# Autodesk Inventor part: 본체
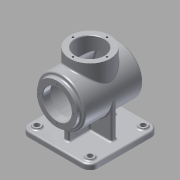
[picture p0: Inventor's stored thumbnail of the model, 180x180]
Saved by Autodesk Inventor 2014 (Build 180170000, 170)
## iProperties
Created: 2015-07
Part Number: 본체
Material: 알루미늄 6061
Document SubType Name: Modeling
Designer: L-10
Density: 2.71 g/cm^3
Appearance: 알루미늄 - 평지
Mass: 1277.59 g
Surface Area: 1269.15 cm^2
Volume: 471.436 cm^3
Author: L-10
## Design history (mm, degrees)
sketch "스케치2"
  geometry: C1 r 45 at (0, 0); 1 further point
  constraints: 1 centre point, 1 coincident
  dimensions: "d0" = 90 diameter of C1
extrude "돌출1" new body sketch "스케치2" stored distance "d1" = 110; taper "d2" = 0 deg
node "작업 평면1"
sketch "스케치3"
  geometry: L1 (-65, -65)-(65, -65); L2 (65, -65)-(65, 65); L3 (65, 65)-(-65, 65); L4 (-65, 65)-(-65, -65); 3 further points
  constraints: 8 end point, 2 midpoint, 2 parallel, 1 horizontal, 1 horizontal alignment, 1 perpendicular, 1 vertical alignment
  dimensions: "d4" = 130 distance of L2.end L3.end; "d5" = 130 distance of L3.end L1.start
extrude "돌출2" join sketch "스케치3" distance "d6" = 10; taper "d7" = 0 deg
sketch "스케치4"
  geometry: C1 r 45 at (0, 0) reference; C2 r 38 at (0, 0)
  constraints: 1 centre point, 1 coincident
  dimensions: "d8" = 76 diameter of C2
extrude "돌출3" join sketch "스케치4" distance "d9" = 7; taper "d10" = 0 deg
sketch "스케치5"
  geometry: L1 (-65, 65)-(-65, -65) reference; L2 (-5, 45)-(-5, 5); L3 (-5, 5)-(-45, 5); L4 (-45, 5)-(-45, -5); L5 (-45, -5)-(-5, -5); L6 (-5, -5)-(-5, -45); L7 (-5, -45)-(5, -45); L8 (5, -45)-(5, -5); L9 (5, -5)-(45, -5); L10 (45, -5)-(45, 5); L11 (45, 5)-(5, 5); L12 (5, 5)-(5, 45); L13 (5, 45)-(-5, 45); 3 further points
  constraints: 24 end point, 9 parallel, 6 collinear, 2 midpoint, 1 horizontal alignment, 1 perpendicular, 1 vertical alignment
  dimensions: "d11" = 10 distance of L9.end L10.end; "d12" = 10 distance of L12.end L2.start; "d13" = 90 distance between parallel lines of L7 L13; "d14" = 90 distance between parallel lines of L10 L4; "d15" = 45 distance from line of L4 point (0, 0) (= 0.5 x d14); "d16" = 45 distance from line of point (0, 0) L13 (= 0.5 x d13)
extrude "돌출4" join sketch "스케치5" stored distance "d17" = 7; taper "d18" = 0 deg
node "작업 평면2"
sketch "스케치6"
  geometry: C1 r 38 at (0, 0); 1 further point
  constraints: 1 centre point, 1 coincident
  dimensions: "d20" = 76 diameter of C1
extrude "돌출5" join sketch "스케치6" stored distance "d21" = 7; taper "d22" = 0 deg
fillet "모깎기1" dims "d23" = 15
sketch "스케치7"
  geometry: C1 r 7.5 at (50, -50); C2 r 7.5 at (50, 50); A1 r 15 centre (50, -50) between (50, -65) and (65, -50) reference; A2 r 15 centre (50, 50) between (65, 50) and (50, 65) reference; 1 further point
  constraints: 2 centre point, 2 coincident
  dimensions: "d24" = 15 diameter of C1; "d25" = 15 diameter of C2; "d26" = 100 distance of C2.centre C1.centre (derived)
extrude "돌출6" join sketch "스케치7" distance "d27" = 3; taper "d28" = 0 deg
hole "구멍1" diameter "d31" = 10; stored, may be unused: countersink angle "d35" = 90 deg, drill point angle "d37" = 118 deg; dims "d29" = 10, "d30" = 10, "d32" = 6, "d33" = 4, "d34" = 2, "d36" = 8
hole "구멍2" diameter "d40" = 10; stored, may be unused: countersink angle "d44" = 90 deg, drill point angle "d46" = 118 deg; dims "d38" = 10, "d39" = 10, "d41" = 6, "d42" = 4, "d43" = 2, "d45" = 8
hole "구멍3" diameter "d49" = 10; stored, may be unused: countersink angle "d53" = 90 deg, drill point angle "d55" = 118 deg; dims "d47" = 10, "d48" = 10, "d50" = 6, "d51" = 4, "d52" = 2, "d54" = 8
hole "구멍4" diameter "d58" = 10; stored, may be unused: countersink angle "d62" = 90 deg, drill point angle "d64" = 118 deg; dims "d56" = 10, "d57" = 10, "d59" = 6, "d60" = 4, "d61" = 2, "d63" = 8
sketch "스케치8"
  geometry: L1 (-62, 0)-(55, 0); L2 (-62, 38)-(-62, -38) reference; L3 (55, -45)-(55, 45) reference; L4 (-62, 27)-(-48, 27); L5 (-48, 27)-(-48, 40); L6 (-48, 40)-(48, 40); L7 (48, 40)-(48, 0); 2 further points
  constraints: 10 end point, 3 point on line, 2 midpoint, 2 parallel, 2 perpendicular, 1 horizontal, 1 horizontal alignment
  dimensions: "d65" = 80 diameter of L6 L1; "d66" = 7 distance between parallel lines of L3 L7; "d67" = 14 distance between parallel lines of L2 L5; "d68" = 54 diameter of L4 L1
revolve "회전1" sketch "스케치8" stored, may be unused: angle "d69" = 90 deg
hole "구멍5" diameter "d72" = 54; stored, may be unused: countersink angle "d76" = 90 deg, drill point angle "d78" = 118 deg; dims "d70" = 10, "d71" = 10, "d73" = 6, "d74" = 4, "d75" = 2, "d77" = 8
fillet "모깎기2" dims "d79" = 3
chamfer "모따기1" distance "d80" = 1; stored, may be unused: second distance "d81" = 2, angle "d82" = 45 deg
sketch "스케치9"
  geometry: C1 r 27 at (0, 0) reference; 1 further point
  constraints: 1 vertical alignment
  dimensions: "d83" = 32 distance of C1.centre point (0, 32)
hole "구멍6" sketch "스케치9" at (0, 32) diameter "d84" = 3.459; stored, may be unused: countersink angle "d88" = 90 deg, drill point angle "d90" = 118 deg; dims "d85" = 8, "d86" = 4, "d87" = 2, "d89" = 10
sketch "스케치10"
  geometry: C1 r 38 at (0, 0) reference; 1 further point
  constraints: 1 vertical alignment
  dimensions: "d94" = 32 distance of C1.centre point (0, 32)
hole "구멍7" sketch "스케치10" at (0, 32) diameter "d95" = 3.459; stored, may be unused: countersink angle "d99" = 90 deg, drill point angle "d101" = 118 deg; dims "d96" = 8, "d97" = 4, "d98" = 2, "d100" = 10
fillet "모깎기3" dims "d105" = 3
fillet "모깎기4" dims "d106" = 3
fillet "모깎기5" dims "d107" = 3
fillet "모깎기6" dims "d108" = 3
fillet "모깎기7" dims "d109" = 3
fillet "모깎기8" dims "d110" = 3
sketch "스케치11"
  geometry: C1 r 42 at (0, 0) reference; 1 further point
  constraints: 1 coincident, 1 other
feature "엠보싱1" sketch "스케치11" dims "d111" = 0.5, "d112" = 0
chamfer "모따기2" distance "d113" = 1; stored, may be unused: second distance "d114" = 2, angle "d115" = 45 deg
node "솔리드1"
mirror "대칭1"
pattern_circular "원형 패턴1" dims angle "d92" = 360 deg
pattern_circular "원형 패턴2" dims angle "d103" = 360 deg
other parameters: "d3" = -78
